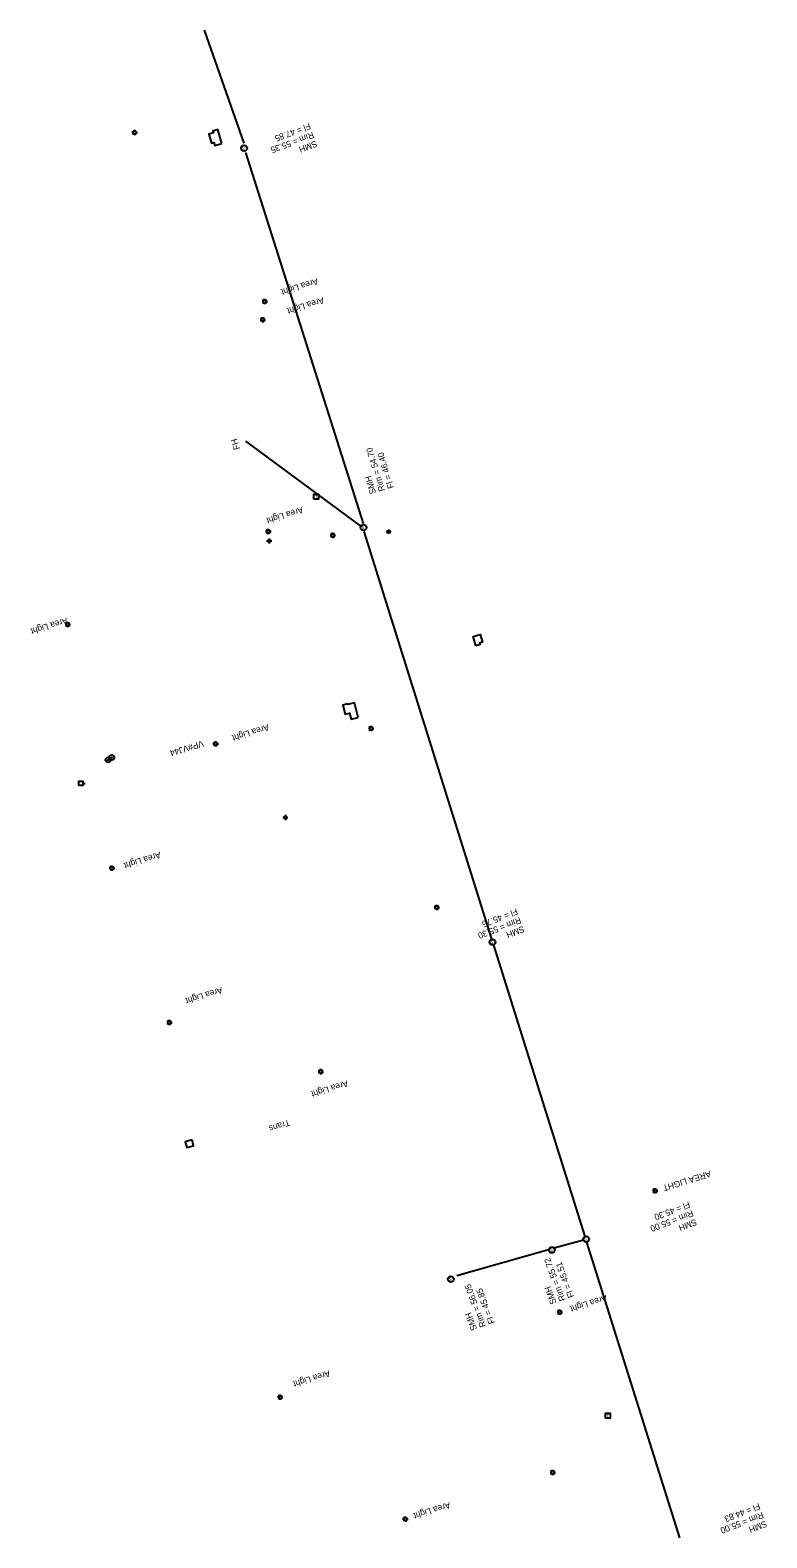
# Model space of a CAD drawing. Extents: x 3872070 to 3879223, y 293944 to 310567.
# Drawn here: x 3874643 to 3874996, y 306589 to 307312 of the extents above; entities that cross this region are included whole.
import ezdxf

# ---------------------------------------------------------------- set-up
doc = ezdxf.new("R2010")
doc.units = 0
for name, color, linetype in [('Level 3', 7, 'Continuous'), ('Level 33', 7, 'Continuous'), ('Level 34', 7, 'Continuous'), ('Level 35', 7, 'Continuous'), ('Level 4', 7, 'Continuous'), ('Level 5', 7, 'Continuous'), ('Level 7', 7, 'Continuous')]:
    doc.layers.add(name, color=color, linetype=linetype)

msp = doc.modelspace()

# ---------------------------------------------------------------- linework, layer by layer
at = {"layer": 'Level 3'}
for p, q in [((3874745.83, 307257.57), (3874726.77, 307311.82)), ((3874803.06, 307075.32), (3874746.57, 307253.14)), ((3874801.58, 307074.22), (3874746.57, 307114.8)), ((3874864.51, 306876.09), (3874803.23, 307071.44)), ((3874909.23, 306733.5), (3874865.41, 306873.19)), ((3874895.41, 306728.24), (3874894.55, 306727.99)), ((3874908.35, 306731.73), (3874895.41, 306728.24)), ((3874954.55, 306589.01), (3874910.09, 306730.76)), ((3874891.63, 306727.15), (3874847.77, 306714.58))]:
    msp.add_line(p, q, dxfattribs=at)
for centre in [(3874745.76, 307255.22), (3874802.98, 307073.35), (3874864.8, 306874.64), (3874893.24, 306727.02), (3874909.67, 306732.19), (3874844.85, 306713)]:
    msp.add_circle(centre, 1.41, dxfattribs=at)
at = {"layer": 'Level 4'}
for p, q in [((3874692.63, 307262.7), (3874692.05, 307262.7)), ((3874692.84, 307263.21), (3874692.43, 307263.61)), ((3874693.35, 307263.42), (3874693.35, 307264)), ((3874693.87, 307263.21), (3874694.27, 307263.61)), ((3874694.08, 307262.7), (3874694.65, 307262.7)), ((3874692.43, 307261.78), (3874692.84, 307262.18)), ((3874693.35, 307261.97), (3874693.35, 307261.4)), ((3874694.27, 307261.78), (3874693.87, 307262.18)), ((3874755.74, 307182.47), (3874755.74, 307183.04)), ((3874755.02, 307181.74), (3874754.44, 307181.74)), ((3874755.23, 307182.25), (3874754.82, 307182.66)), ((3874754.82, 307180.82), (3874755.23, 307181.23)), ((3874755.74, 307181.02), (3874755.74, 307180.44)), ((3874756.25, 307182.25), (3874756.66, 307182.66)), ((3874756.66, 307180.82), (3874756.25, 307181.23)), ((3874756.47, 307181.74), (3874757.04, 307181.74)), ((3874754, 307172.98), (3874753.42, 307172.98)), ((3874754.21, 307173.5), (3874753.8, 307173.9)), ((3874753.8, 307172.07), (3874754.21, 307172.47)), ((3874754.72, 307173.71), (3874754.72, 307174.28)), ((3874754.72, 307172.26), (3874754.72, 307171.68)), ((3874755.23, 307173.5), (3874755.64, 307173.9)), ((3874755.64, 307172.07), (3874755.23, 307172.47)), ((3874755.45, 307172.98), (3874756.02, 307172.98)), ((3874756.64, 307071.49), (3874756.07, 307071.49)), ((3874756.85, 307072), (3874756.45, 307072.41)), ((3874756.45, 307070.57), (3874756.85, 307070.98)), ((3874757.37, 307072.21), (3874757.37, 307072.79)), ((3874757.37, 307070.76), (3874757.37, 307070.19)), ((3874757.88, 307072), (3874758.29, 307072.41)), ((3874758.29, 307070.57), (3874757.88, 307070.98)), ((3874758.09, 307071.49), (3874758.67, 307071.49)), ((3874787.6, 307069.61), (3874787.03, 307069.61)), ((3874787.81, 307070.13), (3874787.41, 307070.53)), ((3874787.41, 307068.7), (3874787.81, 307069.1)), ((3874788.33, 307070.34), (3874788.33, 307070.91)), ((3874788.33, 307068.89), (3874788.33, 307068.32)), ((3874788.84, 307070.13), (3874789.25, 307070.53)), ((3874789.25, 307068.7), (3874788.84, 307069.1)), ((3874789.05, 307069.61), (3874789.63, 307069.61)), ((3874660.54, 307026.89), (3874659.97, 307026.89)), ((3874660.76, 307027.4), (3874660.35, 307027.81)), ((3874660.35, 307025.97), (3874660.76, 307026.38)), ((3874661.27, 307027.61), (3874661.27, 307028.19)), ((3874661.27, 307026.16), (3874661.27, 307025.59)), ((3874661.78, 307027.4), (3874662.19, 307027.81)), ((3874662.19, 307025.97), (3874661.78, 307026.38)), ((3874662, 307026.89), (3874662.57, 307026.89)), ((3874805.97, 306977.02), (3874805.4, 306977.02)), ((3874806.19, 306977.53), (3874805.78, 306977.94)), ((3874805.78, 306976.1), (3874806.19, 306976.51)), ((3874806.7, 306977.74), (3874806.7, 306978.32)), ((3874806.7, 306976.29), (3874806.7, 306975.72)), ((3874807.21, 306977.53), (3874807.62, 306977.94)), ((3874807.62, 306976.1), (3874807.21, 306976.51)), ((3874807.42, 306977.02), (3874808, 306977.02)), ((3874731.42, 306969.63), (3874730.85, 306969.63)), ((3874731.64, 306970.14), (3874731.23, 306970.55)), ((3874731.23, 306968.71), (3874731.64, 306969.12)), ((3874732.15, 306970.36), (3874732.15, 306970.93)), ((3874732.15, 306968.91), (3874732.15, 306968.33)), ((3874732.66, 306970.14), (3874733.07, 306970.55)), ((3874733.07, 306968.71), (3874732.66, 306969.12)), ((3874732.87, 306969.63), (3874733.45, 306969.63)), ((3874668.54, 306950.73), (3874669.54, 306950.73)), ((3874681.73, 306910.12), (3874681.16, 306910.12)), ((3874681.94, 306910.63), (3874681.54, 306911.04)), ((3874681.54, 306909.2), (3874681.94, 306909.61)), ((3874682.46, 306910.85), (3874682.46, 306911.42)), ((3874682.46, 306909.4), (3874682.46, 306908.82)), ((3874682.97, 306910.63), (3874683.37, 306911.04)), ((3874683.37, 306909.2), (3874682.97, 306909.61)), ((3874683.18, 306910.12), (3874683.75, 306910.12)), ((3874837.41, 306891.26), (3874836.83, 306891.26)), ((3874837.62, 306891.77), (3874837.21, 306892.17)), ((3874837.21, 306890.34), (3874837.62, 306890.74)), ((3874838.13, 306891.98), (3874838.13, 306892.56)), ((3874838.13, 306890.53), (3874838.13, 306889.96)), ((3874838.64, 306891.77), (3874839.05, 306892.17)), ((3874839.05, 306890.34), (3874838.64, 306890.74)), ((3874838.86, 306891.26), (3874839.43, 306891.26)), ((3874709.24, 306836.05), (3874708.67, 306836.05)), ((3874709.45, 306836.56), (3874709.05, 306836.97)), ((3874709.96, 306836.77), (3874709.96, 306837.35)), ((3874710.48, 306836.56), (3874710.88, 306836.97)), ((3874710.69, 306836.05), (3874711.27, 306836.05)), ((3874709.05, 306835.13), (3874709.45, 306835.54)), ((3874709.96, 306835.32), (3874709.96, 306834.75)), ((3874710.88, 306835.13), (3874710.48, 306835.54)), ((3874781.83, 306812.48), (3874781.26, 306812.48)), ((3874782.05, 306812.99), (3874781.64, 306813.4)), ((3874781.64, 306811.56), (3874782.05, 306811.97)), ((3874782.56, 306813.2), (3874782.56, 306813.78)), ((3874782.56, 306811.75), (3874782.56, 306811.18)), ((3874783.07, 306812.99), (3874783.48, 306813.4)), ((3874783.48, 306811.56), (3874783.07, 306811.97)), ((3874783.28, 306812.48), (3874783.86, 306812.48)), ((3874942.77, 306756.08), (3874942.77, 306756.66)), ((3874942.04, 306755.36), (3874941.47, 306755.36)), ((3874942.26, 306755.87), (3874941.85, 306756.28)), ((3874941.85, 306754.44), (3874942.26, 306754.85)), ((3874942.77, 306754.63), (3874942.77, 306754.06)), ((3874943.28, 306755.87), (3874943.69, 306756.28)), ((3874943.69, 306754.44), (3874943.28, 306754.85)), ((3874943.49, 306755.36), (3874944.07, 306755.36)), ((3874897.06, 306697.93), (3874897.06, 306698.51)), ((3874896.34, 306697.21), (3874895.76, 306697.21)), ((3874896.55, 306697.72), (3874896.14, 306698.12)), ((3874896.14, 306696.29), (3874896.55, 306696.69)), ((3874897.06, 306696.48), (3874897.06, 306695.91)), ((3874897.58, 306697.72), (3874897.98, 306698.12)), ((3874897.98, 306696.29), (3874897.58, 306696.69)), ((3874897.79, 306697.21), (3874898.36, 306697.21)), ((3874762.37, 306656.42), (3874761.79, 306656.42)), ((3874762.58, 306656.94), (3874762.18, 306657.34)), ((3874762.18, 306655.51), (3874762.58, 306655.91)), ((3874763.1, 306657.15), (3874763.1, 306657.72)), ((3874763.1, 306655.7), (3874763.1, 306655.12)), ((3874763.61, 306656.94), (3874764.01, 306657.34)), ((3874764.01, 306655.51), (3874763.61, 306655.91)), ((3874763.82, 306656.42), (3874764.4, 306656.42)), ((3874893.02, 306620.33), (3874892.45, 306620.33)), ((3874893.23, 306620.84), (3874892.83, 306621.25)), ((3874892.83, 306619.41), (3874893.23, 306619.82)), ((3874893.75, 306621.06), (3874893.75, 306621.63)), ((3874893.75, 306619.61), (3874893.75, 306619.03)), ((3874894.26, 306620.84), (3874894.66, 306621.25)), ((3874894.66, 306619.41), (3874894.26, 306619.82)), ((3874894.47, 306620.33), (3874895.04, 306620.33)), ((3874822.32, 306598.01), (3874821.74, 306598.01)), ((3874822.53, 306598.53), (3874822.12, 306598.93)), ((3874822.12, 306597.09), (3874822.53, 306597.5)), ((3874823.04, 306598.74), (3874823.04, 306599.31)), ((3874823.04, 306597.29), (3874823.04, 306596.71)), ((3874823.55, 306598.53), (3874823.96, 306598.93)), ((3874823.96, 306597.09), (3874823.55, 306597.5)), ((3874823.77, 306598.01), (3874824.34, 306598.01))]:
    msp.add_line(p, q, dxfattribs=at)
for points in [[(3874735.12, 307257.51), (3874733.21, 307264.13), (3874730.83, 307263.44), (3874731.08, 307262.57), (3874728.94, 307261.95), (3874730.16, 307257.7), (3874731.28, 307258.02), (3874731.71, 307256.53), (3874731.8, 307256.55), (3874735.12, 307257.51)], [(3874856.88, 307016.62), (3874855.51, 307021.08), (3874858.93, 307022.12), (3874860.08, 307018.38), (3874858.63, 307017.94), (3874858.83, 307017.27), (3874858.84, 307017.23), (3874856.88, 307016.62)], [(3874800.44, 306982.36), (3874798.7, 306989.34), (3874795.45, 306988.53), (3874795.38, 306988.84), (3874793.03, 306988.25), (3874794.14, 306983.83), (3874796.31, 306984.37), (3874797.02, 306981.51), (3874800.44, 306982.36)], [(3874720.81, 306779.79), (3874717.5, 306778.87), (3874718.27, 306776.08), (3874721.58, 306777), (3874720.81, 306779.79)]]:
    msp.add_lwpolyline(points, dxfattribs=at)
msp.add_lwpolyline([(3874666.54, 306949.73), (3874666.54, 306951.73), (3874668.54, 306951.73), (3874668.54, 306949.73)], close=True, dxfattribs=at)
for centre, radius in [((3874693.35, 307262.7), 0.725), ((3874755.74, 307181.74), 0.725), ((3874754.72, 307172.98), 0.725), ((3874757.37, 307071.49), 0.725), ((3874788.33, 307069.61), 0.725), ((3874661.27, 307026.89), 0.725), ((3874806.7, 306977.02), 0.725), ((3874732.15, 306969.63), 0.725), ((3874680.62, 306961.98), 1.22), ((3874680.62, 306961.98), 0.0992), ((3874680.62, 306961.98), 0.0483), ((3874682.36, 306963.1), 1.22), ((3874682.36, 306963.1), 0.0992), ((3874682.36, 306963.1), 0.0483), ((3874682.46, 306910.12), 0.725), ((3874838.13, 306891.26), 0.725), ((3874709.96, 306836.05), 0.725), ((3874782.56, 306812.48), 0.725), ((3874942.77, 306755.36), 0.725), ((3874897.06, 306697.21), 0.725), ((3874763.1, 306656.42), 0.725), ((3874893.75, 306620.33), 0.725), ((3874823.04, 306598.01), 0.725)]:
    msp.add_circle(centre, radius, dxfattribs=at)
at = {"layer": 'Level 5'}
for p, q in [((3874757.82, 307068.17), (3874757.82, 307067.54)), ((3874814.56, 307071.36), (3874814.2, 307071.36)), ((3874815.56, 307071.36), (3874814.56, 307071.36)), ((3874815.92, 307071.36), (3874815.56, 307071.36)), ((3874756.57, 307066.92), (3874757.19, 307066.92)), ((3874757.82, 307066.3), (3874757.82, 307065.67)), ((3874758.44, 307066.92), (3874759.07, 307066.92)), ((3874764.3, 306934.34), (3874764.92, 306934.34)), ((3874765.55, 306935.59), (3874765.55, 306934.95)), ((3874765.55, 306933.71), (3874765.55, 306933.09)), ((3874766.16, 306934.34), (3874766.8, 306934.34))]:
    msp.add_line(p, q, dxfattribs=at)
for centre, radius in [((3874757.82, 307066.92), 0.625), ((3874815.06, 307071.36), 0.7), ((3874765.55, 306934.34), 0.625)]:
    msp.add_circle(centre, radius, dxfattribs=at)
msp.add_arc((3874815.06, 307071.36), 0.5, 180, 0, dxfattribs=at)
at = {"layer": 'Level 7'}
for points in [[(3874779.22, 307086.92), (3874779.22, 307089.32), (3874781.41, 307089.32), (3874781.41, 307086.92)], [(3874919.01, 306646.35), (3874919.01, 306648.75), (3874921.2, 306648.75), (3874921.2, 306646.35)]]:
    msp.add_lwpolyline(points, close=True, dxfattribs=at)

# ---------------------------------------------------------------- texts
at = {"layer": 'Level 3'}
for p in [(3874746.23, 307255.93), (3874803.46, 307074.06), (3874865.27, 306875.35), (3874893.71, 306727.74), (3874910.15, 306732.9), (3874845.33, 306713.71)]:
    msp.add_text('S', height=1.41, rotation=180, dxfattribs=at).set_placement(p)
at = {"layer": 'Level 33'}
for s, rotation, p in [('Rim = 55.35', 200.41106, (3874778.55, 307263.15)), ('Fl = 47.85', 200.41106, (3874776.98, 307267.37)), ('SMH', 200.41106, (3874780.12, 307258.94)), ('Rim = 54.70', 106.83751, (3874813.37, 307091.22)), ('Fl = 46.40', 106.83751, (3874817.68, 307092.53)), ('SMH', 106.83751, (3874809.07, 307089.92)), ('Rim = 55.30', 201.00467, (3874877.81, 306886.65)), ('Fl = 45.75', 201.00467, (3874876.2, 306890.85)), ('SMH', 201.00467, (3874879.42, 306882.45)), ('Fl = 45.30', 201.00467, (3874958.79, 306750.37)), ('Rim = 55.00', 201.00467, (3874960.4, 306746.16)), ('SMH', 201.00467, (3874962.01, 306741.96)), ('Rim = 55.72', 110.35413, (3874899.84, 306703.12)), ('Fl = 45.51', 110.35413, (3874904.06, 306704.69)), ('Rim = 56.05', 110.35413, (3874861.73, 306690.59)), ('Fl = 45.85', 110.35413, (3874865.95, 306692.15)), ('SMH', 110.35413, (3874895.62, 306701.56)), ('SMH', 110.35413, (3874857.52, 306689.02)), ('Fl = 44.83', 201.00467, (3874992.4, 306605.7)), ('Rim = 55.00', 201.00467, (3874994.01, 306601.5)), ('SMH', 201.00467, (3874995.62, 306597.3))]:
    msp.add_text(s, height=3, rotation=rotation, dxfattribs=at).set_placement(p)
at = {"layer": 'Level 34'}
for s, rotation, p in [('Area Light', 197.24972, (3874780.7, 307192.98)), ('Area Light', 197.24972, (3874783.58, 307183.87)), ('Area Light', 197.24972, (3874773.62, 307083.37)), ('Area Light', 197.24972, (3874660.68, 307030.29)), ('Area Light', 197.24972, (3874757.19, 306979.12)), ('VP#VJ44', 196.9281, (3874725.87, 306971.41)), ('Area Light', 197.24972, (3874705.3, 306917.98)), ('Area Light', 197.24972, (3874734.91, 306853.14)), ('Area Light', 197.24972, (3874795.1, 306808.42)), ('Trans', 198.37632, (3874767.13, 306789.64)), ('AREA LIGHT', 197.24972, (3874968.94, 306765.06)), ('Area Light', 197.24972, (3874919.19, 306705.46)), ('Area Light', 197.24972, (3874786.49, 306669.4)), ('Area Light', 197.24972, (3874844.14, 306606.24))]:
    msp.add_text(s, height=3, rotation=rotation, dxfattribs=at).set_placement(p)
at = {"layer": 'Level 35'}
msp.add_text('FH', height=3, rotation=106.96876, dxfattribs=at).set_placement((3874743.85, 307111.16))
at = {"layer": 'Level 7'}
for p in [(3874779.74, 307087.35), (3874919.53, 306646.78)]:
    msp.add_text('T', height=1.41, dxfattribs=at).set_placement(p)

doc.saveas('drawing.dxf')
